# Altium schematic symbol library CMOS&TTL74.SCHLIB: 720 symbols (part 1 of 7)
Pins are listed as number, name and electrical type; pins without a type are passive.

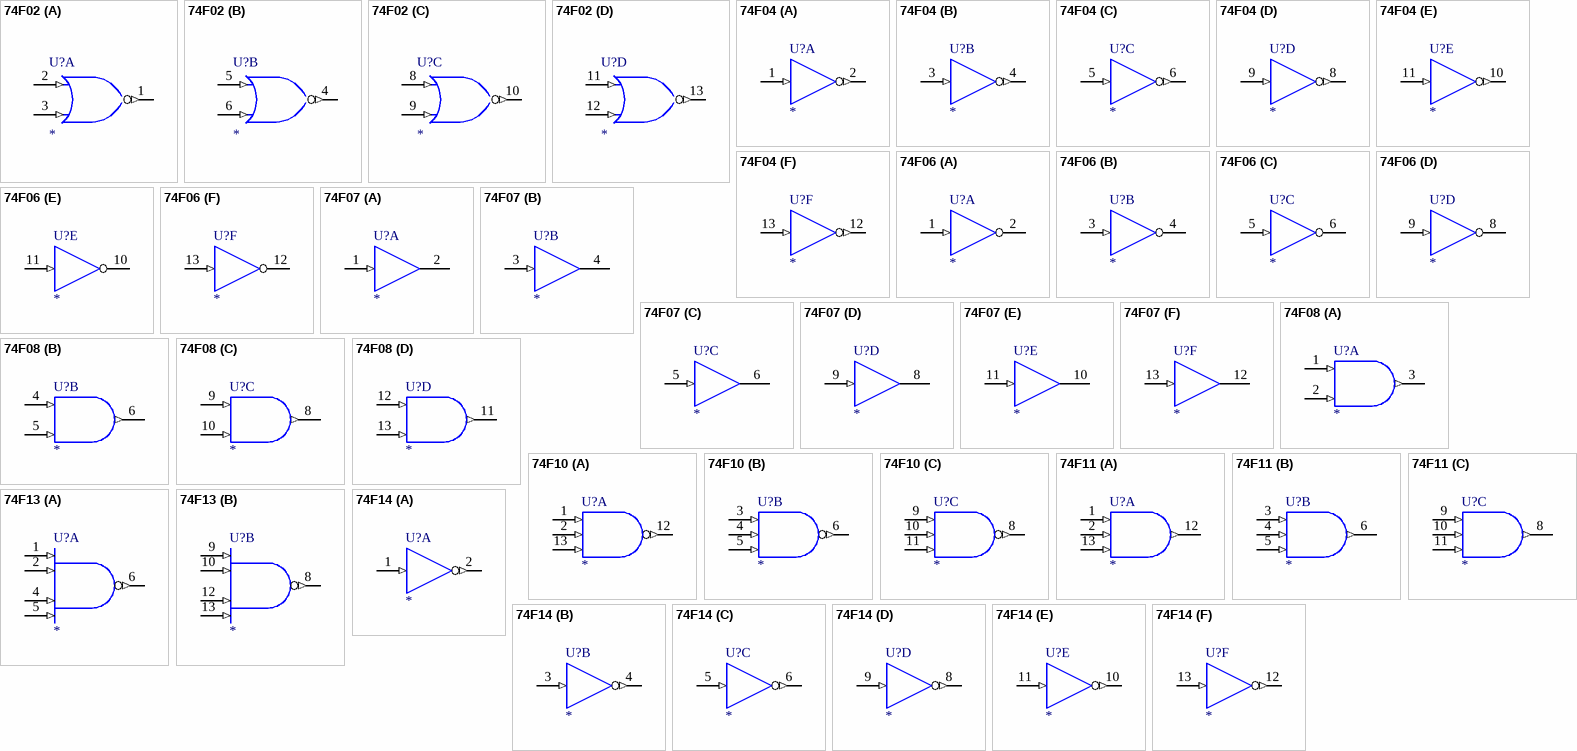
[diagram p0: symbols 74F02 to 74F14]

## 74F02
designator U?
Quad 2-Input NOR Gate
footprint DIP-14
simulation model 74F02 (SIMCODE)
part A pins: 1 Y (out), 2 A (in), 3 B (in), 7 GND (power) hidden to GND, 14 VCC (power) hidden to VCC
part B pins: 4 Y (out), 5 A (in), 6 B (in), 7 GND (power) hidden to GND, 14 VCC (power) hidden to VCC
part C pins: 7 GND (power) hidden to GND, 8 A (in), 9 B (in), 10 Y (out), 14 VCC (power) hidden to VCC
part D pins: 7 GND (power) hidden to GND, 11 A (in), 12 B (in), 13 Y (out), 14 VCC (power) hidden to VCC
1 alternate drawing of the same symbol

## 74F04
designator U?
Hex Inverter
footprint DIP-14
simulation model 74F04 (SIMCODE)
part A pins: 1 A (in), 2 Y (out), 7 GND (power) hidden to GND, 14 VCC (power) hidden to VCC
part B pins: 3 A (in), 4 Y (out), 7 GND (power) hidden to GND, 14 VCC (power) hidden to VCC
part C pins: 5 A (in), 6 Y (out), 7 GND (power) hidden to GND, 14 VCC (power) hidden to VCC
part D pins: 7 GND (power) hidden to GND, 8 Y (out), 9 A (in), 14 VCC (power) hidden to VCC
part E pins: 7 GND (power) hidden to GND, 10 Y (out), 11 A (in), 14 VCC (power) hidden to VCC
part F pins: 7 GND (power) hidden to GND, 12 Y (out), 13 A (in), 14 VCC (power) hidden to VCC
1 alternate drawing of the same symbol

## 74F06
designator U?
Hex Inverter with Open-Collector High-Voltage Output
footprint DIP-14
simulation model 74F06 (SIMCODE)
part A pins: 1 A (in), 2 Y (oc), 7 GND (power) hidden to GND, 14 VCC (power) hidden to VCC
part B pins: 3 A (in), 4 Y (oc), 7 GND (power) hidden to GND, 14 VCC (power) hidden to VCC
part C pins: 5 A (in), 6 Y (oc), 7 GND (power) hidden to GND, 14 VCC (power) hidden to VCC
part D pins: 7 GND (power) hidden to GND, 8 Y (oc), 9 A (in), 14 VCC (power) hidden to VCC
part E pins: 7 GND (power) hidden to GND, 10 Y (oc), 11 A (in), 14 VCC (power) hidden to VCC
part F pins: 7 GND (power) hidden to GND, 12 Y (oc), 13 A (in), 14 VCC (power) hidden to VCC
2 alternate drawings of the same symbol

## 74F07
designator U?
Hex Buffer/Driver with Open-Collector High-Voltage Output
footprint DIP-14
simulation model 74F07 (SIMCODE)
part A pins: 1 A (in), 2 Y (oc), 7 GND (power) hidden to GND, 14 VCC (power) hidden to VCC
part B pins: 3 A (in), 4 Y (oc), 7 GND (power) hidden to GND, 14 VCC (power) hidden to VCC
part C pins: 5 A (in), 6 Y (oc), 7 GND (power) hidden to GND, 14 VCC (power) hidden to VCC
part D pins: 7 GND (power) hidden to GND, 8 Y (oc), 9 A (in), 14 VCC (power) hidden to VCC
part E pins: 7 GND (power) hidden to GND, 10 Y (oc), 11 A (in), 14 VCC (power) hidden to VCC
part F pins: 7 GND (power) hidden to GND, 12 Y (oc), 13 A (in), 14 VCC (power) hidden to VCC
2 alternate drawings of the same symbol

## 74F08
designator U?
Quad 2-Input Positive-AND Gate
footprint DIP-14
simulation model 74F08 (SIMCODE)
part A pins: 1 A (in), 2 B (in), 3 Y (out), 7 GND (power) hidden to GND, 14 VCC (power) hidden to VCC
part B pins: 4 A (in), 5 B (in), 6 Y (out), 7 GND (power) hidden to GND, 14 VCC (power) hidden to VCC
part C pins: 7 GND (power) hidden to GND, 8 Y (out), 9 A (in), 10 B (in), 14 VCC (power) hidden to VCC
part D pins: 7 GND (power) hidden to GND, 11 Y (out), 12 A (in), 13 B (in), 14 VCC (power) hidden to VCC
1 alternate drawing of the same symbol

## 74F10
designator U?
Triple 3-Input Positive-NAND Gate
footprint DIP-14
simulation model 74F10 (SIMCODE)
part A pins: 1 A (in), 2 B (in), 7 GND (power) hidden to GND, 12 Y (out), 13 C (in), 14 VCC (power) hidden to VCC
part B pins: 3 A (in), 4 B (in), 5 C (in), 6 Y (out), 7 GND (power) hidden to GND, 14 VCC (power) hidden to VCC
part C pins: 7 GND (power) hidden to GND, 8 Y (out), 9 A (in), 10 B (in), 11 C (in), 14 VCC (power) hidden to VCC
1 alternate drawing of the same symbol

## 74F11
designator U?
Triple 3-Input Positive-AND Gate
footprint DIP-14
simulation model 74F11 (SIMCODE)
part A pins: 1 A (in), 2 B (in), 7 GND (power) hidden to GND, 12 Y (out), 13 C (in), 14 VCC (power) hidden to VCC
part B pins: 3 A (in), 4 B (in), 5 C (in), 6 Y (out), 7 GND (power) hidden to GND, 14 VCC (power) hidden to VCC
part C pins: 7 GND (power) hidden to GND, 8 Y (out), 9 A (in), 10 B (in), 11 C (in), 14 VCC (power) hidden to VCC
1 alternate drawing of the same symbol

## 74F13
designator U?
Dual 4-Input Positive-NAND Schmitt-Trigger
footprint DIP-14
simulation model 74F13 (SIMCODE)
part A pins: 1 A (in), 2 B (in), 4 C (in), 5 D (in), 6 Y (out), 7 GND (power) hidden to GND, 14 VCC (power) hidden to VCC
part B pins: 7 GND (power) hidden to GND, 8 Y (out), 9 A (in), 10 B (in), 12 C (in), 13 D (in), 14 VCC (power) hidden to VCC
1 alternate drawing of the same symbol

## 74F14
designator U?
Hex Schmitt-Trigger Inverter
footprint DIP-14
simulation model 74F14 (SIMCODE)
part A pins: 1 A (in), 2 Y (out), 7 GND (power) hidden to GND, 14 VCC (power) hidden to VCC
part B pins: 3 A (in), 4 Y (out), 7 GND (power) hidden to GND, 14 VCC (power) hidden to VCC
part C pins: 5 A (in), 6 Y (out), 7 GND (power) hidden to GND, 14 VCC (power) hidden to VCC
part D pins: 7 GND (power) hidden to GND, 8 Y (out), 9 A (in), 14 VCC (power) hidden to VCC
part E pins: 7 GND (power) hidden to GND, 10 Y (out), 11 A (in), 14 VCC (power) hidden to VCC
part F pins: 7 GND (power) hidden to GND, 12 Y (out), 13 A (in), 14 VCC (power) hidden to VCC
1 alternate drawing of the same symbol

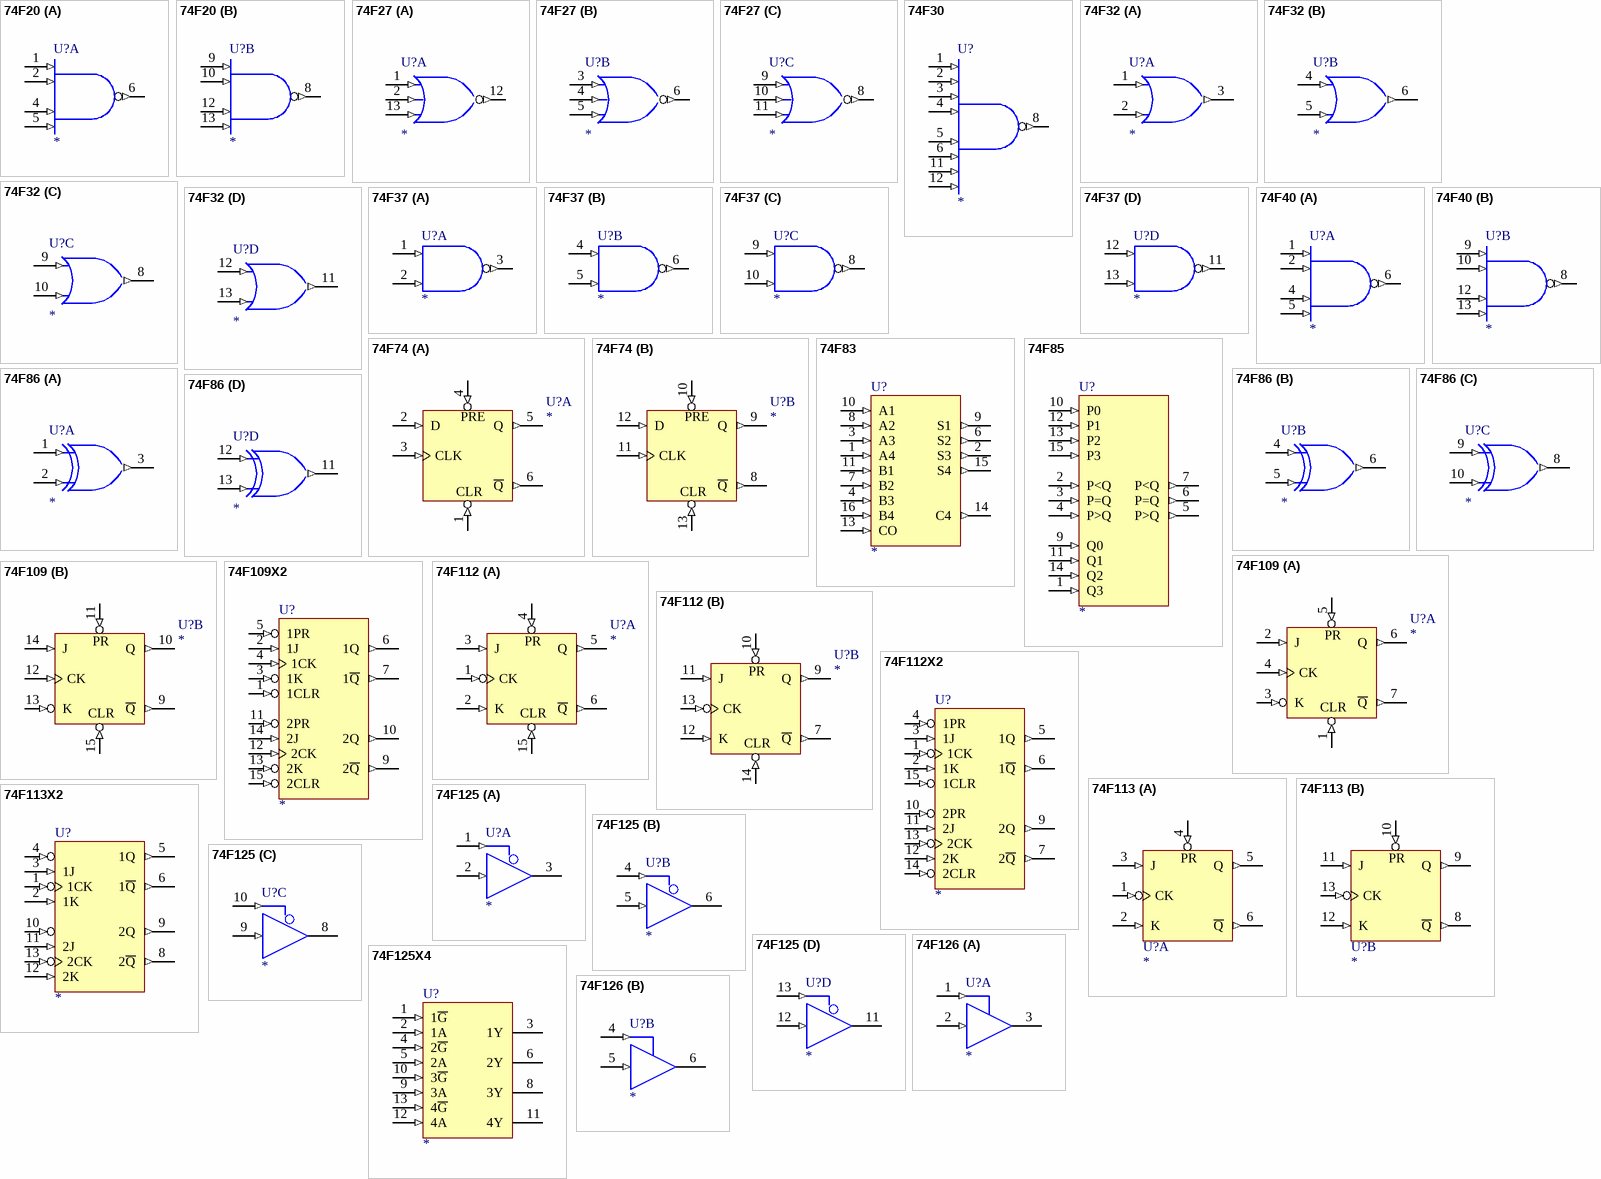
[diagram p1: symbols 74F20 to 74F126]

## 74F20
designator U?
Dual 4-Input Positive-NAND Gate
footprint DIP-14
simulation model 74F20 (SIMCODE)
part A pins: 1 A (in), 2 B (in), 4 C (in), 5 D (in), 6 Y (out), 7 GND (power) hidden to GND, 14 VCC (power) hidden to VCC
part B pins: 7 GND (power) hidden to GND, 8 Y (out), 9 A (in), 10 B (in), 12 C (in), 13 D (in), 14 VCC (power) hidden to VCC
2 alternate drawings of the same symbol

## 74F27
designator U?
Triple 3-Input Positive-NOR Gate
footprint DIP-14
simulation model 74F27 (SIMCODE)
part A pins: 1 A (in), 2 B (in), 7 GND (power) hidden to GND, 12 Y (out), 13 C (in), 14 VCC (power) hidden to VCC
part B pins: 3 A (in), 4 B (in), 5 C (in), 6 Y (out), 7 GND (power) hidden to GND, 14 VCC (power) hidden to VCC
part C pins: 7 GND (power) hidden to GND, 8 Y (out), 9 A (in), 10 B (in), 11 C (in), 14 VCC (power) hidden to VCC
1 alternate drawing of the same symbol

## 74F30
designator U?
8-Input Positive-NAND Gate
footprint DIP-14
simulation model 74F30 (SIMCODE)
pins: 1 A (in), 2 B (in), 3 C (in), 4 D (in), 5 E (in), 6 F (in), 7 GND (power) hidden to GND, 8 Y (out), 11 G (in), 12 H (in), 14 VCC (power) hidden to VCC
1 alternate drawing of the same symbol

## 74F32
designator U?
Quad 2-Input Positive-OR Gate
footprint DIP-14
simulation model 74F32 (SIMCODE)
part A pins: 1 A (in), 2 B (in), 3 Y (out), 7 GND (power) hidden to GND, 14 VCC (power) hidden to VCC
part B pins: 4 A (in), 5 B (in), 6 Y (out), 7 GND (power) hidden to GND, 14 VCC (power) hidden to VCC
part C pins: 7 GND (power) hidden to GND, 8 Y (out), 9 A (in), 10 B (in), 14 VCC (power) hidden to VCC
part D pins: 7 GND (power) hidden to GND, 11 Y (out), 12 A (in), 13 B (in), 14 VCC (power) hidden to VCC
1 alternate drawing of the same symbol

## 74F37
designator U?
Quad 2-Input Positive-NAND Buffer
footprint DIP-14
simulation model 74F37 (SIMCODE)
part A pins: 1 A (in), 2 B (in), 3 Y (out), 7 GND (power) hidden to GND, 14 VCC (power) hidden to VCC
part B pins: 4 A (in), 5 B (in), 6 Y (out), 7 GND (power) hidden to GND, 14 VCC (power) hidden to VCC
part C pins: 7 GND (power) hidden to GND, 8 Y (out), 9 A (in), 10 B (in), 14 VCC (power) hidden to VCC
part D pins: 7 GND (power) hidden to GND, 11 Y (out), 12 A (in), 13 B (in), 14 VCC (power) hidden to VCC
1 alternate drawing of the same symbol

## 74F40
designator U?
Dual 4-Input Positive-NAND Buffer
footprint DIP-14
simulation model 74F40 (SIMCODE)
part A pins: 1 A (in), 2 B (in), 4 C (in), 5 D (in), 6 Y (out), 7 GND (power) hidden to GND, 14 VCC (power) hidden to VCC
part B pins: 7 GND (power) hidden to GND, 8 Y (out), 9 A (in), 10 B (in), 12 C (in), 13 D (in), 14 VCC (power) hidden to VCC
2 alternate drawings of the same symbol

## 74F74
designator U?
Dual D-Type Positive-Edge-Triggered Flip-Flop with Clear and Preset
footprint DIP-14
simulation model 74F74 (SIMCODE)
part A pins: 1 ~{CLR} (in), 2 D (in), 3 CLK (in), 4 ~{PRE} (in), 5 Q (out), 6 ~{Q} (out), 7 GND (power) hidden to GND, 14 VCC (power) hidden to VCC
part B pins: 7 GND (power) hidden to GND, 8 ~{Q} (out), 9 Q (out), 10 ~{PRE} (in), 11 CLK (in), 12 D (in), 13 ~{CLR} (in), 14 VCC (power) hidden to VCC
1 alternate drawing of the same symbol

## 74F83
designator U?
4-Bit Binary Full Adder with Fast Carry
footprint DIP-16
simulation model 74F83 (SIMCODE)
pins: 1 A4 (in), 2 S3 (out), 3 A3 (in), 4 B3 (in), 5 VCC (power) hidden to VCC, 6 S2 (out), 7 B2 (in), 8 A2 (in), 9 S1 (out), 10 A1 (in), 11 B1 (in), 12 GND (power) hidden to GND, 13 CO (in), 14 C4 (out), 15 S4 (out), 16 B4 (in)
1 alternate drawing of the same symbol

## 74F85
designator U?
4-Bit Magnitude Comparator
footprint DIP-16
simulation model 74F85 (SIMCODE)
pins: 1 Q3 (in), 2 P<Q (in), 3 P=Q (in), 4 P>Q (in), 5 P>Q (out), 6 P=Q (out), 7 P<Q (out), 8 GND (power) hidden to GND, 9 Q0 (in), 10 P0 (in), 11 Q1 (in), 12 P1 (in), 13 P2 (in), 14 Q2 (in), 15 P3 (in), 16 VCC (power) hidden to VCC
1 alternate drawing of the same symbol

## 74F86
designator U?
Quad Exclusive-OR Gate
footprint DIP-14
simulation model 74F86 (SIMCODE)
part A pins: 1 A (in), 2 B (in), 3 Y (out), 7 GND (power) hidden to GND, 14 VCC (power) hidden to VCC
part B pins: 4 A (in), 5 B (in), 6 Y (out), 7 GND (power) hidden to GND, 14 VCC (power) hidden to VCC
part C pins: 7 GND (power) hidden to GND, 8 Y (out), 9 A (in), 10 B (in), 14 VCC (power) hidden to VCC
part D pins: 7 GND (power) hidden to GND, 11 Y (out), 12 A (in), 13 B (in), 14 VCC (power) hidden to VCC
1 alternate drawing of the same symbol

## 74F109
designator U?
Dual J-~K Positive-Edge-Triggered Flip Flop with Preset and Clear
footprint DIP-16
simulation model 74F109 (SIMCODE)
part A pins: 1 CLR (in), 2 J (in), 3 K (in), 4 CK (in), 5 PR (in), 6 Q (out), 7 ~{Q} (out), 8 GND (power) hidden to GND, 16 VCC (power) hidden to VCC
part B pins: 8 GND (power) hidden to GND, 9 ~{Q} (out), 10 Q (out), 11 PR (in), 12 CK (in), 13 K (in), 14 J (in), 15 CLR (in), 16 VCC (power) hidden to VCC
1 alternate drawing of the same symbol

## 74F109X2
designator U?
Dual J-~K Positive-Edge-Triggered Flip Flop with Preset and Clear
footprint DIP-16
simulation model 74F109X2 (SIMCODE)
pins: 1 1CLR (in), 2 1J (in), 3 1K (in), 4 1CK (in), 5 1PR (in), 6 1Q (out), 7 1~{Q} (out), 8 GND (power) hidden to GND, 9 2~{Q} (out), 10 2Q (out), 11 2PR (in), 12 2CK (in), 13 2K (in), 14 2J (in), 15 2CLR (in), 16 VCC (power) hidden to VCC
1 alternate drawing of the same symbol

## 74F112
designator U?
Dual J-K Negative-Edge-Triggered Flip-Flop with Clear and Preset
footprint DIP-16
simulation model 74F112 (SIMCODE)
part A pins: 1 CK (in), 2 K (in), 3 J (in), 4 PR (in), 5 Q (out), 6 ~{Q} (out), 8 GND (power) hidden to GND, 15 CLR (in), 16 VCC (power) hidden to VCC
part B pins: 7 ~{Q} (out), 8 GND (power) hidden to GND, 9 Q (out), 10 PR (in), 11 J (in), 12 K (in), 13 CK (in), 14 CLR (in), 16 VCC (power) hidden to VCC
1 alternate drawing of the same symbol

## 74F112X2
designator U?
Dual J-K Negative-Edge-Triggered Flip-Flop with Clear and Preset
footprint DIP-16
simulation model 74F112X2 (SIMCODE)
pins: 1 1CK (in), 2 1K (in), 3 1J (in), 4 1PR (in), 5 1Q (out), 6 1~{Q} (out), 7 2~{Q} (out), 8 GND (power) hidden to GND, 9 2Q (out), 10 2PR (in), 11 2J (in), 12 2K (in), 13 2CK (in), 14 2CLR (in), 15 1CLR (in), 16 VCC (power) hidden to VCC
1 alternate drawing of the same symbol

## 74F113
designator U?
Dual J-K Negative-Edge-Triggered Flip-Flop with Preset
footprint DIP-14
simulation model 74F113 (SIMCODE)
part A pins: 1 CK (in), 2 K (in), 3 J (in), 4 PR (in), 5 Q (out), 6 ~{Q} (out), 7 GND (power) hidden to GND, 14 VCC (power) hidden to VCC
part B pins: 7 GND (power) hidden to GND, 8 ~{Q} (out), 9 Q (out), 10 PR (in), 11 J (in), 12 K (in), 13 CK (in), 14 VCC (power) hidden to VCC
1 alternate drawing of the same symbol

## 74F113X2
designator U?
Dual J-K Negative-Edge-Triggered Flip-Flop with Preset
footprint DIP-14
simulation model 74F113X2 (SIMCODE)
pins: 1 1CK (in), 2 1K (in), 3 1J (in), 4 1PR (in), 5 1Q (out), 6 1~{Q} (out), 7 GND (power) hidden to GND, 8 2~{Q} (out), 9 2Q (out), 10 2PR (in), 11 2J (in), 12 2K (in), 13 2CK (in), 14 VCC (power) hidden to VCC
1 alternate drawing of the same symbol

## 74F125
designator U?
Quad Bus Buffer Gate with 3-State Output
footprint DIP-14
simulation model 74F125 (SIMCODE)
part A pins: 1 ~{G} (in), 2 A (in), 3 Y (hiz), 7 GND (power) hidden to GND, 14 VCC (power) hidden to VCC
part B pins: 4 ~{G} (in), 5 A (in), 6 Y (hiz), 7 GND (power) hidden to GND, 14 VCC (power) hidden to VCC
part C pins: 7 GND (power) hidden to GND, 8 Y (hiz), 9 A (in), 10 ~{G} (in), 14 VCC (power) hidden to VCC
part D pins: 7 GND (power) hidden to GND, 11 Y (hiz), 12 A (in), 13 ~{G} (in), 14 VCC (power) hidden to VCC
1 alternate drawing of the same symbol

## 74F125X4
designator U?
Quad Bus Buffer Gate with 3-State Output
footprint DIP-14
simulation model 74F125X4 (SIMCODE)
pins: 1 1~{G} (in), 2 1A (in), 3 1Y (hiz), 4 2~{G} (in), 5 2A (in), 6 2Y (hiz), 7 GND (power) hidden to GND, 8 3Y (hiz), 9 3A (in), 10 3~{G} (in), 11 4Y (hiz), 12 4A (in), 13 4~{G} (in), 14 VCC (power) hidden to VCC
1 alternate drawing of the same symbol

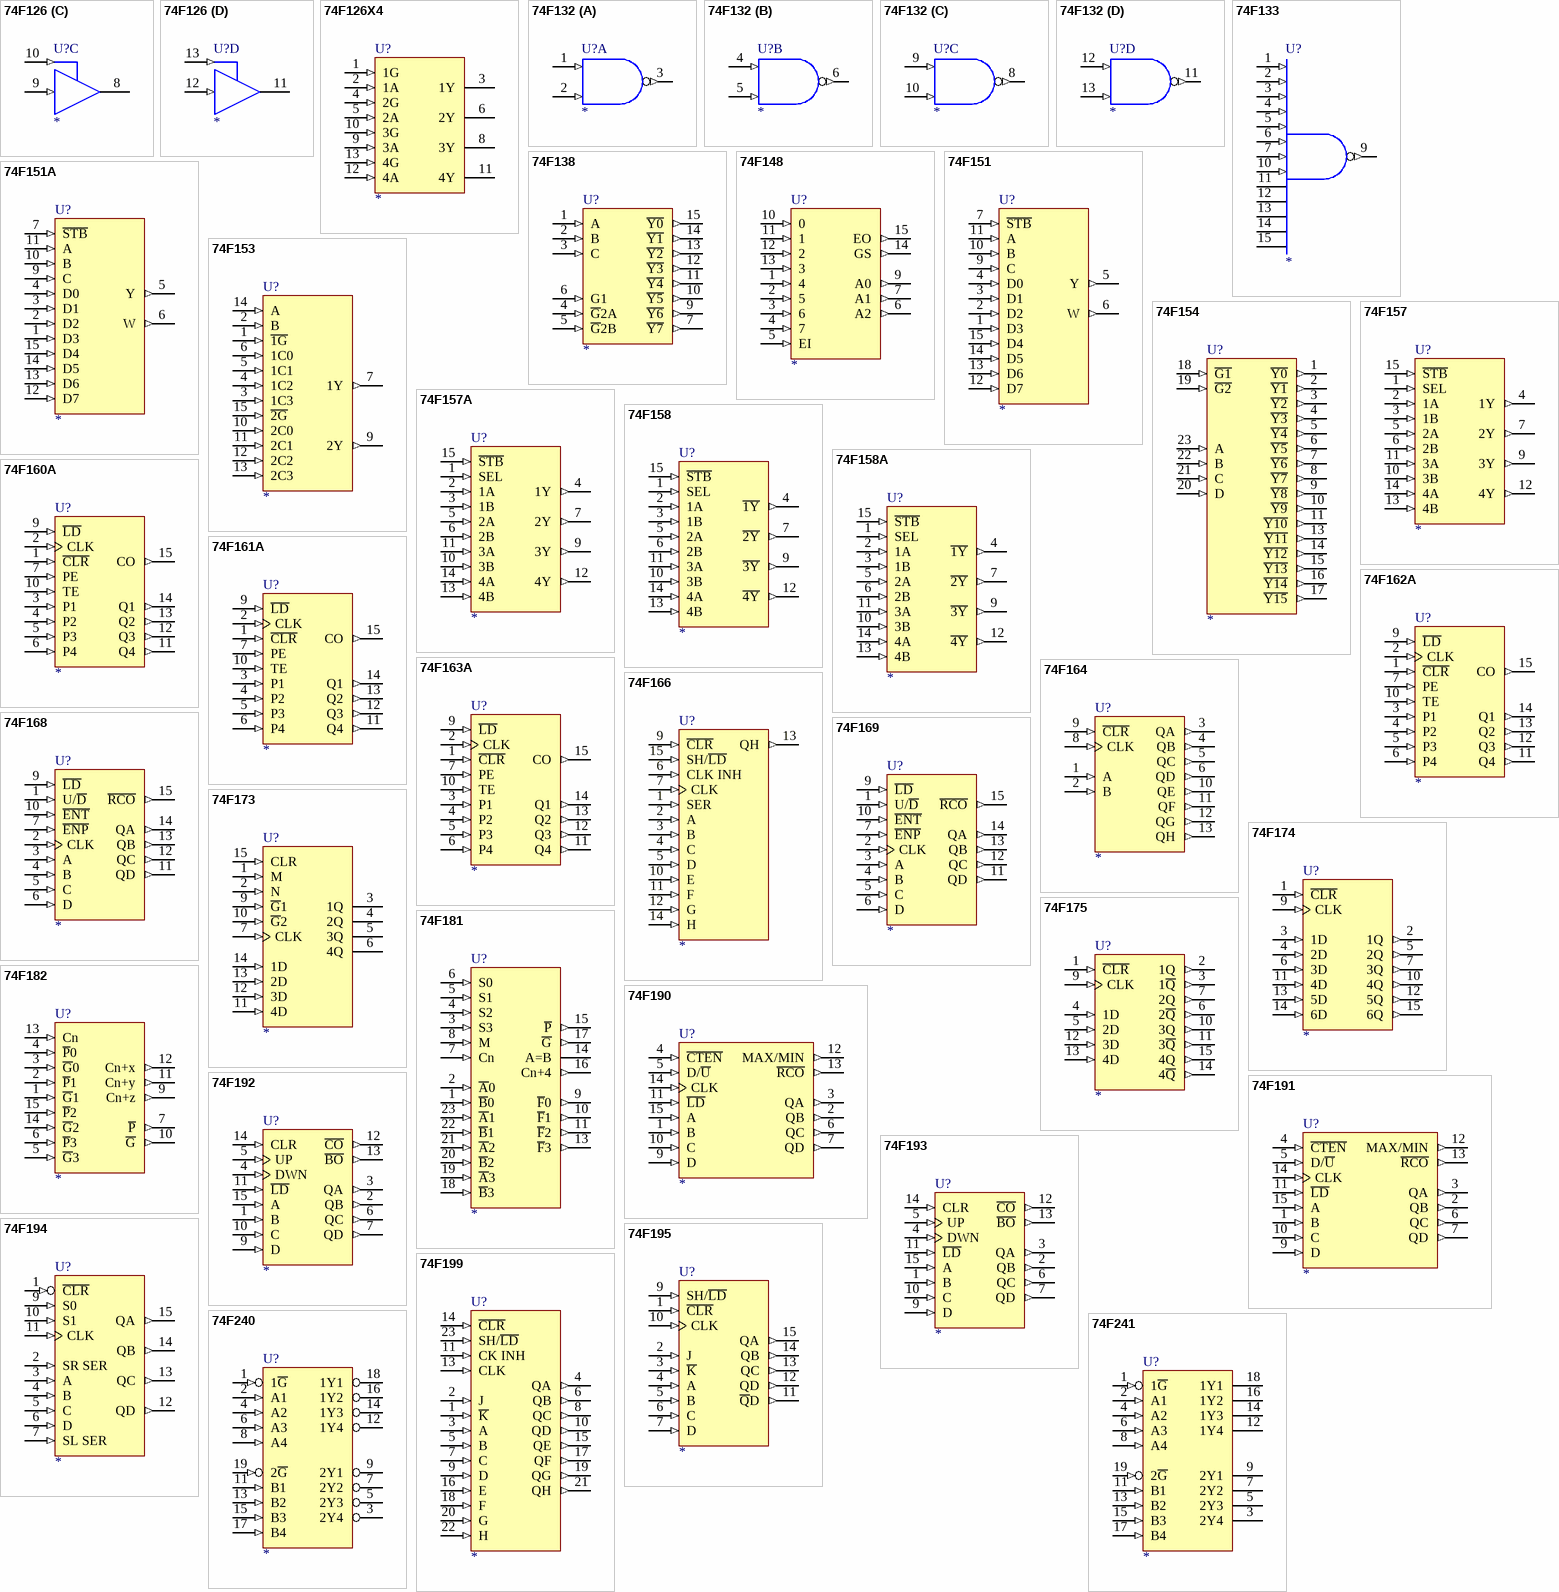
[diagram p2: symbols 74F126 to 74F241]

## 74F126
designator U?
Quad Bus Buffer Gate with 3-State Output
footprint DIP-14
simulation model 74F126 (SIMCODE)
part A pins: 1 G (in), 2 A (in), 3 Y (hiz), 7 GND (power) hidden to GND, 14 VCC (power) hidden to VCC
part B pins: 4 G (in), 5 A (in), 6 Y (hiz), 7 GND (power) hidden to GND, 14 VCC (power) hidden to VCC
part C pins: 7 GND (power) hidden to GND, 8 Y (hiz), 9 A (in), 10 G (in), 14 VCC (power) hidden to VCC
part D pins: 7 GND (power) hidden to GND, 11 Y (hiz), 12 A (in), 13 G (in), 14 VCC (power) hidden to VCC
1 alternate drawing of the same symbol

## 74F126X4
designator U?
Quad Bus Buffer Gate with 3-State Output
footprint DIP-14
simulation model 74F126X4 (SIMCODE)
pins: 1 1G (in), 2 1A (in), 3 1Y (hiz), 4 2G (in), 5 2A (in), 6 2Y (hiz), 7 GND (power) hidden to GND, 8 3Y (hiz), 9 3A (in), 10 3G (in), 11 4Y (hiz), 12 4A (in), 13 4G (in), 14 VCC (power) hidden to VCC
1 alternate drawing of the same symbol

## 74F132
designator U?
Quad Positive-NAND Gate with Schmitt-Trigger Input
footprint DIP-14
simulation model 74F132 (SIMCODE)
part A pins: 1 A (in), 2 B (in), 3 Y (out), 7 GND (power) hidden to GND, 14 VCC (power) hidden to VCC
part B pins: 4 A (in), 5 B (in), 6 Y (out), 7 GND (power) hidden to GND, 14 VCC (power) hidden to VCC
part C pins: 7 GND (power) hidden to GND, 8 Y (out), 9 A (in), 10 B (in), 14 VCC (power) hidden to VCC
part D pins: 7 GND (power) hidden to GND, 11 Y (out), 12 A (in), 13 B (in), 14 VCC (power) hidden to VCC
1 alternate drawing of the same symbol

## 74F133
designator U?
13-Input Positive-NAND Gate
footprint DIP-16
simulation model 74F133 (SIMCODE)
pins: 1 A (in), 2 B (in), 3 C (in), 4 D (in), 5 E (in), 6 F (in), 7 G (in), 8 GND (power) hidden to GND, 9 Y (out), 10 H (in), 11 I, 12 J, 13 K, 14 L, 15 M, 16 VCC (power) hidden to VCC
2 alternate drawings of the same symbol

## 74F138
designator U?
3-Line to 8-Line Decoder/Demultiplexer
footprint DIP-16
simulation model 74F138 (SIMCODE)
pins: 1 A (in), 2 B (in), 3 C (in), 4 ~{G}2A (in), 5 ~{G}2B (in), 6 G1 (in), 7 ~{Y7} (out), 8 GND (power) hidden to GND, 9 ~{Y6} (out), 10 ~{Y5} (out), 11 ~{Y4} (out), 12 ~{Y3} (out), 13 ~{Y2} (out), 14 ~{Y1} (out), 15 ~{Y0} (out), 16 VCC (power) hidden to VCC
1 alternate drawing of the same symbol

## 74F148
designator U?
8-Line to 3-Line Priority Encoder
footprint DIP-16
simulation model 74F148 (SIMCODE)
pins: 1 4 (in), 2 5 (in), 3 6 (in), 4 7 (in), 5 EI (in), 6 A2 (out), 7 A1 (out), 8 GND (power) hidden to GND, 9 A0 (out), 10 0 (in), 11 1 (in), 12 2 (in), 13 3 (in), 14 GS (out), 15 EO (out), 16 VCC (power) hidden to VCC
1 alternate drawing of the same symbol

## 74F151
designator U?
1 of 8 Data Selector/Multiplexer
footprint DIP-16
simulation model 74F151 (SIMCODE)
pins: 1 D3 (in), 2 D2 (in), 3 D1 (in), 4 D0 (in), 5 Y (out), 6 W (out), 7 ~{STB} (in), 8 GND (power) hidden to GND, 9 C (in), 10 B (in), 11 A (in), 12 D7 (in), 13 D6 (in), 14 D5 (in), 15 D4 (in), 16 VCC (power) hidden to VCC
1 alternate drawing of the same symbol

## 74F151A
designator U?
1 of 8 Data Selector/Multiplexer
footprint DIP-16
simulation model 74F151A (SIMCODE)
pins: 1 D3 (in), 2 D2 (in), 3 D1 (in), 4 D0 (in), 5 Y (out), 6 W (out), 7 ~{STB} (in), 8 GND (power) hidden to GND, 9 C (in), 10 B (in), 11 A (in), 12 D7 (in), 13 D6 (in), 14 D5 (in), 15 D4 (in), 16 VCC (power) hidden to VCC
1 alternate drawing of the same symbol

## 74F153
designator U?
Dual 4-Line to 1-Line Data Selector/Multiplexer
footprint DIP-16
simulation model 74F153 (SIMCODE)
pins: 1 ~{1G} (in), 2 B (in), 3 1C3 (in), 4 1C2 (in), 5 1C1 (in), 6 1C0 (in), 7 1Y (out), 8 GND (power) hidden to GND, 9 2Y (out), 10 2C0 (in), 11 2C1 (in), 12 2C2 (in), 13 2C3 (in), 14 A (in), 15 ~{2G} (in), 16 VCC (power) hidden to VCC
1 alternate drawing of the same symbol

## 74F154
designator U?
4-Line to 16-Line Decoder/Demultiplexer
footprint DIP-24
simulation model 74F154 (SIMCODE)
pins: 1 ~{Y0} (out), 2 ~{Y1} (out), 3 ~{Y2} (out), 4 ~{Y3} (out), 5 ~{Y4} (out), 6 ~{Y5} (out), 7 ~{Y6} (out), 8 ~{Y7} (out), 9 ~{Y8} (out), 10 ~{Y9} (out), 11 ~{Y10} (out), 12 GND (power) hidden to GND, 13 ~{Y11} (out), 14 ~{Y12} (out), 15 ~{Y13} (out), 16 ~{Y14} (out), 17 ~{Y15} (out), 18 ~{G1} (in), 19 ~{G2} (in), 20 D (in), 21 C (in), 22 B (in), 23 A (in), 24 VCC (power) hidden to VCC
1 alternate drawing of the same symbol

## 74F157
designator U?
Quad 2-Line to 1-Line Data Selector/Multiplexer
footprint DIP-16
simulation model 74F157 (SIMCODE)
pins: 1 SEL (in), 2 1A (in), 3 1B (in), 4 1Y (out), 5 2A (in), 6 2B (in), 7 2Y (out), 8 GND (power) hidden to GND, 9 3Y (out), 10 3B (in), 11 3A (in), 12 4Y (out), 13 4B (in), 14 4A (in), 15 ~{STB} (in), 16 VCC (power) hidden to VCC
1 alternate drawing of the same symbol

## 74F157A
designator U?
Quad 2-Line to 1-Line Data Selector/Multiplexer
footprint DIP-16
simulation model 74F157A (SIMCODE)
pins: 1 SEL (in), 2 1A (in), 3 1B (in), 4 1Y (out), 5 2A (in), 6 2B (in), 7 2Y (out), 8 GND (power) hidden to GND, 9 3Y (out), 10 3B (in), 11 3A (in), 12 4Y (out), 13 4B (in), 14 4A (in), 15 ~{STB} (in), 16 VCC (power) hidden to VCC
1 alternate drawing of the same symbol

## 74F158
designator U?
Quad 2-Line to 1-Line Data Selector/Multiplexer
footprint DIP-16
simulation model 74F158 (SIMCODE)
pins: 1 SEL (in), 2 1A (in), 3 1B (in), 4 ~{1Y} (out), 5 2A (in), 6 2B (in), 7 ~{2Y} (out), 8 GND (power) hidden to GND, 9 ~{3Y} (out), 10 3B (in), 11 3A (in), 12 ~{4Y} (out), 13 4B (in), 14 4A (in), 15 ~{STB} (in), 16 VCC (power) hidden to VCC
1 alternate drawing of the same symbol

## 74F158A
designator U?
Quad 2-Line to 1-Line Data Selector/Multiplexer
footprint DIP-16
simulation model 74F158A (SIMCODE)
pins: 1 SEL (in), 2 1A (in), 3 1B (in), 4 ~{1Y} (out), 5 2A (in), 6 2B (in), 7 ~{2Y} (out), 8 GND (power) hidden to GND, 9 ~{3Y} (out), 10 3B (in), 11 3A (in), 12 ~{4Y} (out), 13 4B (in), 14 4A (in), 15 ~{STB} (in), 16 VCC (power) hidden to VCC
1 alternate drawing of the same symbol

## 74F160A
designator U?
Synchronous 4-Bit Decade Counter with Direct Clear
footprint DIP-16
simulation model 74F160A (SIMCODE)
pins: 1 ~{CLR} (in), 2 CLK (in), 3 P1 (in), 4 P2 (in), 5 P3 (in), 6 P4 (in), 7 PE (in), 8 GND (power) hidden to GND, 9 ~{LD} (in), 10 TE (in), 11 Q4 (out), 12 Q3 (out), 13 Q2 (out), 14 Q1 (out), 15 CO (out), 16 VCC (power) hidden to VCC
1 alternate drawing of the same symbol

## 74F161A
designator U?
Synchronous 4-Bit Binary Counter with Direct Clear
footprint DIP-16
simulation model 74F161A (SIMCODE)
pins: 1 ~{CLR} (in), 2 CLK (in), 3 P1 (in), 4 P2 (in), 5 P3 (in), 6 P4 (in), 7 PE (in), 8 GND (power) hidden to GND, 9 ~{LD} (in), 10 TE (in), 11 Q4 (out), 12 Q3 (out), 13 Q2 (out), 14 Q1 (out), 15 CO (out), 16 VCC (power) hidden to VCC
1 alternate drawing of the same symbol

## 74F162A
designator U?
Fully Synchronous 4-Bit Decade Counter
footprint DIP-16
simulation model 74F162A (SIMCODE)
pins: 1 ~{CLR} (in), 2 CLK (in), 3 P1 (in), 4 P2 (in), 5 P3 (in), 6 P4 (in), 7 PE (in), 8 GND (power) hidden to GND, 9 ~{LD} (in), 10 TE (in), 11 Q4 (out), 12 Q3 (out), 13 Q2 (out), 14 Q1 (out), 15 CO (out), 16 VCC (power) hidden to VCC
1 alternate drawing of the same symbol

## 74F163A
designator U?
Fully Synchronous 4-Bit Binary Counter
footprint DIP-16
simulation model 74F163A (SIMCODE)
pins: 1 ~{CLR} (in), 2 CLK (in), 3 P1 (in), 4 P2 (in), 5 P3 (in), 6 P4 (in), 7 PE (in), 8 GND (power) hidden to GND, 9 ~{LD} (in), 10 TE (in), 11 Q4 (out), 12 Q3 (out), 13 Q2 (out), 14 Q1 (out), 15 CO (out), 16 VCC (power) hidden to VCC
1 alternate drawing of the same symbol

## 74F164
designator U?
8-Bit Parallel-Out Serial Shift Register
footprint DIP-14
simulation model 74F164 (SIMCODE)
pins: 1 A (in), 2 B (in), 3 QA (out), 4 QB (out), 5 QC (out), 6 QD (out), 7 GND (power) hidden to GND, 8 CLK (in), 9 ~{CLR} (in), 10 QE (out), 11 QF (out), 12 QG (out), 13 QH (out), 14 VCC (power) hidden to VCC
1 alternate drawing of the same symbol

## 74F166
designator U?
Parallel-Load 8-Bit Shift Register
footprint DIP-16
simulation model 74F166 (SIMCODE)
pins: 1 SER (in), 2 A (in), 3 B (in), 4 C (in), 5 D (in), 6 CLK INH (in), 7 CLK (in), 8 GND (power) hidden to GND, 9 ~{CLR} (in), 10 E (in), 11 F (in), 12 G (in), 13 QH (out), 14 H (in), 15 SH/~{LD} (in), 16 VCC (power) hidden to VCC
1 alternate drawing of the same symbol

## 74F168
designator U?
Synchronous 4-Bit Up/Down Decade Counter
footprint DIP-16
simulation model 74F168 (SIMCODE)
pins: 1 U/~{D} (in), 2 CLK (in), 3 A (in), 4 B (in), 5 C (in), 6 D (in), 7 ~{ENP} (in), 8 GND (power) hidden to GND, 9 ~{LD} (in), 10 ~{ENT} (in), 11 QD (out), 12 QC (out), 13 QB (out), 14 QA (out), 15 ~{RCO} (out), 16 VCC (power) hidden to VCC
1 alternate drawing of the same symbol

## 74F169
designator U?
Synchronous 4-Bit Up/Down Decade Counter
footprint DIP-16
simulation model 74F169 (SIMCODE)
pins: 1 U/~{D} (in), 2 CLK (in), 3 A (in), 4 B (in), 5 C (in), 6 D (in), 7 ~{ENP} (in), 8 GND (power) hidden to GND, 9 ~{LD} (in), 10 ~{ENT} (in), 11 QD (out), 12 QC (out), 13 QB (out), 14 QA (out), 15 ~{RCO} (out), 16 VCC (power) hidden to VCC
1 alternate drawing of the same symbol

## 74F173
designator U?
4-Bit D-Type Register with 3-State Outputs
footprint DIP-16
simulation model 74F173 (SIMCODE)
pins: 1 M (in), 2 N (in), 3 1Q (hiz), 4 2Q (hiz), 5 3Q (hiz), 6 4Q (hiz), 7 CLK (in), 8 GND (power) hidden to GND, 9 ~{G}1 (in), 10 ~{G}2 (in), 11 4D (in), 12 3D (in), 13 2D (in), 14 1D (in), 15 CLR (in), 16 VCC (power) hidden to VCC
1 alternate drawing of the same symbol

## 74F174
designator U?
Hex D-Type Flip-Flop with Clear
footprint DIP-16
simulation model 74F174 (SIMCODE)
pins: 1 ~{CLR} (in), 2 1Q (out), 3 1D (in), 4 2D (in), 5 2Q (out), 6 3D (in), 7 3Q (out), 8 GND (power) hidden to GND, 9 CLK (in), 10 4Q (out), 11 4D (in), 12 5Q (out), 13 5D (in), 14 6D (in), 15 6Q (out), 16 VCC (power) hidden to VCC
1 alternate drawing of the same symbol

## 74F175
designator U?
Quad D-Type Flip-Flop with Clear
footprint DIP-16
simulation model 74F175 (SIMCODE)
pins: 1 ~{CLR} (in), 2 1Q (out), 3 1~{Q} (out), 4 1D (in), 5 2D (in), 6 2~{Q} (out), 7 2Q (out), 8 GND (power) hidden to GND, 9 CLK (in), 10 3Q (out), 11 3~{Q} (out), 12 3D (in), 13 4D (in), 14 4~{Q} (out), 15 4Q (out), 16 VCC (power) hidden to VCC
1 alternate drawing of the same symbol

## 74F181
designator U?
Arithmetic Logic Unit/Function Generator
footprint DIP-24
simulation model 74F181 (SIMCODE)
pins: 1 ~{B}0 (in), 2 ~{A}0 (in), 3 S3 (in), 4 S2 (in), 5 S1 (in), 6 S0 (in), 7 Cn (in), 8 M (in), 9 ~{F}0 (out), 10 ~{F}1 (out), 11 ~{F}2 (out), 12 GND (power) hidden to GND, 13 ~{F}3 (out), 14 A=B (oc), 15 ~{P} (out), 16 Cn+4 (out), 17 ~{G} (out), 18 ~{B}3 (in), 19 ~{A}3 (in), 20 ~{B}2 (in), 21 ~{A}2 (in), 22 ~{B}1 (in), 23 ~{A}1 (in), 24 VCC (power) hidden to VCC
1 alternate drawing of the same symbol

## 74F182
designator U?
Look-Ahead Carry Generator
footprint DIP-16
simulation model 74F182 (SIMCODE)
pins: 1 ~{G}1 (in), 2 ~{P}1 (in), 3 ~{G}0 (in), 4 ~{P}0 (in), 5 ~{G}3 (in), 6 ~{P}3 (in), 7 ~{P} (out), 8 GND (power) hidden to GND, 9 Cn+z (out), 10 ~{G} (out), 11 Cn+y (out), 12 Cn+x (out), 13 Cn (in), 14 ~{G}2 (in), 15 ~{P}2 (in), 16 VCC (power) hidden to VCC
1 alternate drawing of the same symbol

## 74F190
designator U?
Synchronous 4-Bit Up/Down Decade Counter with Down/Up Mode Control
footprint DIP-16
simulation model 74F190 (SIMCODE)
pins: 1 B (in), 2 QB (out), 3 QA (out), 4 ~{CTEN} (in), 5 D/~{U} (in), 6 QC (out), 7 QD (out), 8 GND (power) hidden to GND, 9 D (in), 10 C (in), 11 ~{LD} (in), 12 MAX/MIN (out), 13 ~{RCO} (out), 14 CLK (in), 15 A (in), 16 VCC (power) hidden to VCC
1 alternate drawing of the same symbol

## 74F191
designator U?
Synchronous 4-Bit Up/Down Binary Counter with Down/Up Mode Control
footprint DIP-16
simulation model 74F191 (SIMCODE)
pins: 1 B (in), 2 QB (out), 3 QA (out), 4 ~{CTEN} (in), 5 D/~{U} (in), 6 QC (out), 7 QD (out), 8 GND (power) hidden to GND, 9 D (in), 10 C (in), 11 ~{LD} (in), 12 MAX/MIN (out), 13 ~{RCO} (out), 14 CLK (in), 15 A (in), 16 VCC (power) hidden to VCC
1 alternate drawing of the same symbol

## 74F192
designator U?
Synchronous 4-Bit Up/Down Decade Counter (Dual Clock with Clear)
footprint DIP-16
simulation model 74F192 (SIMCODE)
pins: 1 B (in), 2 QB (out), 3 QA (out), 4 DWN (in), 5 UP (in), 6 QC (out), 7 QD (out), 8 GND (power) hidden to GND, 9 D (in), 10 C (in), 11 ~{LD} (in), 12 ~{CO} (out), 13 ~{BO} (out), 14 CLR (in), 15 A (in), 16 VCC (power) hidden to VCC
1 alternate drawing of the same symbol

## 74F193
designator U?
Synchronous 4-Bit Up/Down Binary Counter (Dual Clock with Clear)
footprint DIP-16
simulation model 74F193 (SIMCODE)
pins: 1 B (in), 2 QB (out), 3 QA (out), 4 DWN (in), 5 UP (in), 6 QC (out), 7 QD (out), 8 GND (power) hidden to GND, 9 D (in), 10 C (in), 11 ~{LD} (in), 12 ~{CO} (out), 13 ~{BO} (out), 14 CLR (in), 15 A (in), 16 VCC (power) hidden to VCC
1 alternate drawing of the same symbol

## 74F194
designator U?
4-Bit Bidirectional Universal Shift Register
footprint DIP-16
simulation model 74F194 (SIMCODE)
pins: 1 ~{CLR} (in), 2 SR SER (in), 3 A (in), 4 B (in), 5 C (in), 6 D (in), 7 SL SER (in), 8 GND (power) hidden to GND, 9 S0 (in), 10 S1 (in), 11 CLK (in), 12 QD (out), 13 QC (out), 14 QB (out), 15 QA (out), 16 VCC (power) hidden to VCC
1 alternate drawing of the same symbol

## 74F195
designator U?
4-Bit Parallel-Access Shift Register
footprint DIP-16
simulation model 74F195 (SIMCODE)
pins: 1 ~{CLR} (in), 2 J (in), 3 ~{K} (in), 4 A (in), 5 B (in), 6 C (in), 7 D (in), 8 GND (power) hidden to GND, 9 SH/~{LD} (in), 10 CLK (in), 11 ~{Q}D (out), 12 QD (out), 13 QC (out), 14 QB (out), 15 QA (out), 16 VCC (power) hidden to VCC
1 alternate drawing of the same symbol

## 74F199
designator U?
8-Bit Shift Register
footprint DIP-24
simulation model 74F199 (SIMCODE)
pins: 1 ~{K} (in), 2 J (in), 3 A (in), 4 QA (out), 5 B (in), 6 QB (out), 7 C (in), 8 QC (out), 9 D (in), 10 QD (out), 11 CK INH (in), 12 GND (power) hidden to GND, 13 CLK (in), 14 ~{CLR} (in), 15 QE (out), 16 E (in), 17 QF (out), 18 F (in), 19 QG (out), 20 G (in), 21 QH (out), 22 H (in), 23 SH/~{LD} (in), 24 VCC (power) hidden to VCC
1 alternate drawing of the same symbol

## 74F240
designator U?
Octal Buffer and Line Driver with 3-State Output
footprint DIP-20
simulation model 74F240 (SIMCODE)
pins: 1 1~{G} (in), 2 A1 (in), 3 2Y4 (hiz), 4 A2 (in), 5 2Y3 (hiz), 6 A3 (in), 7 2Y2 (hiz), 8 A4 (in), 9 2Y1 (hiz), 10 GND (power) hidden to GND, 11 B1 (in), 12 1Y4 (hiz), 13 B2 (in), 14 1Y3 (hiz), 15 B3 (in), 16 1Y2 (hiz), 17 B4 (in), 18 1Y1 (hiz), 19 2~{G} (in), 20 VCC (power) hidden to VCC
1 alternate drawing of the same symbol

## 74F241
designator U?
Octal Buffer and Line Driver with 3-State Output
footprint DIP-20
simulation model 74F241 (SIMCODE)
pins: 1 1~{G} (in), 2 A1 (in), 3 2Y4 (hiz), 4 A2 (in), 5 2Y3 (hiz), 6 A3 (in), 7 2Y2 (hiz), 8 A4 (in), 9 2Y1 (hiz), 10 GND (power) hidden to GND, 11 B1 (in), 12 1Y4 (hiz), 13 B2 (in), 14 1Y3 (hiz), 15 B3 (in), 16 1Y2 (hiz), 17 B4 (in), 18 1Y1 (hiz), 19 2~{G} (in), 20 VCC (power) hidden to VCC
1 alternate drawing of the same symbol

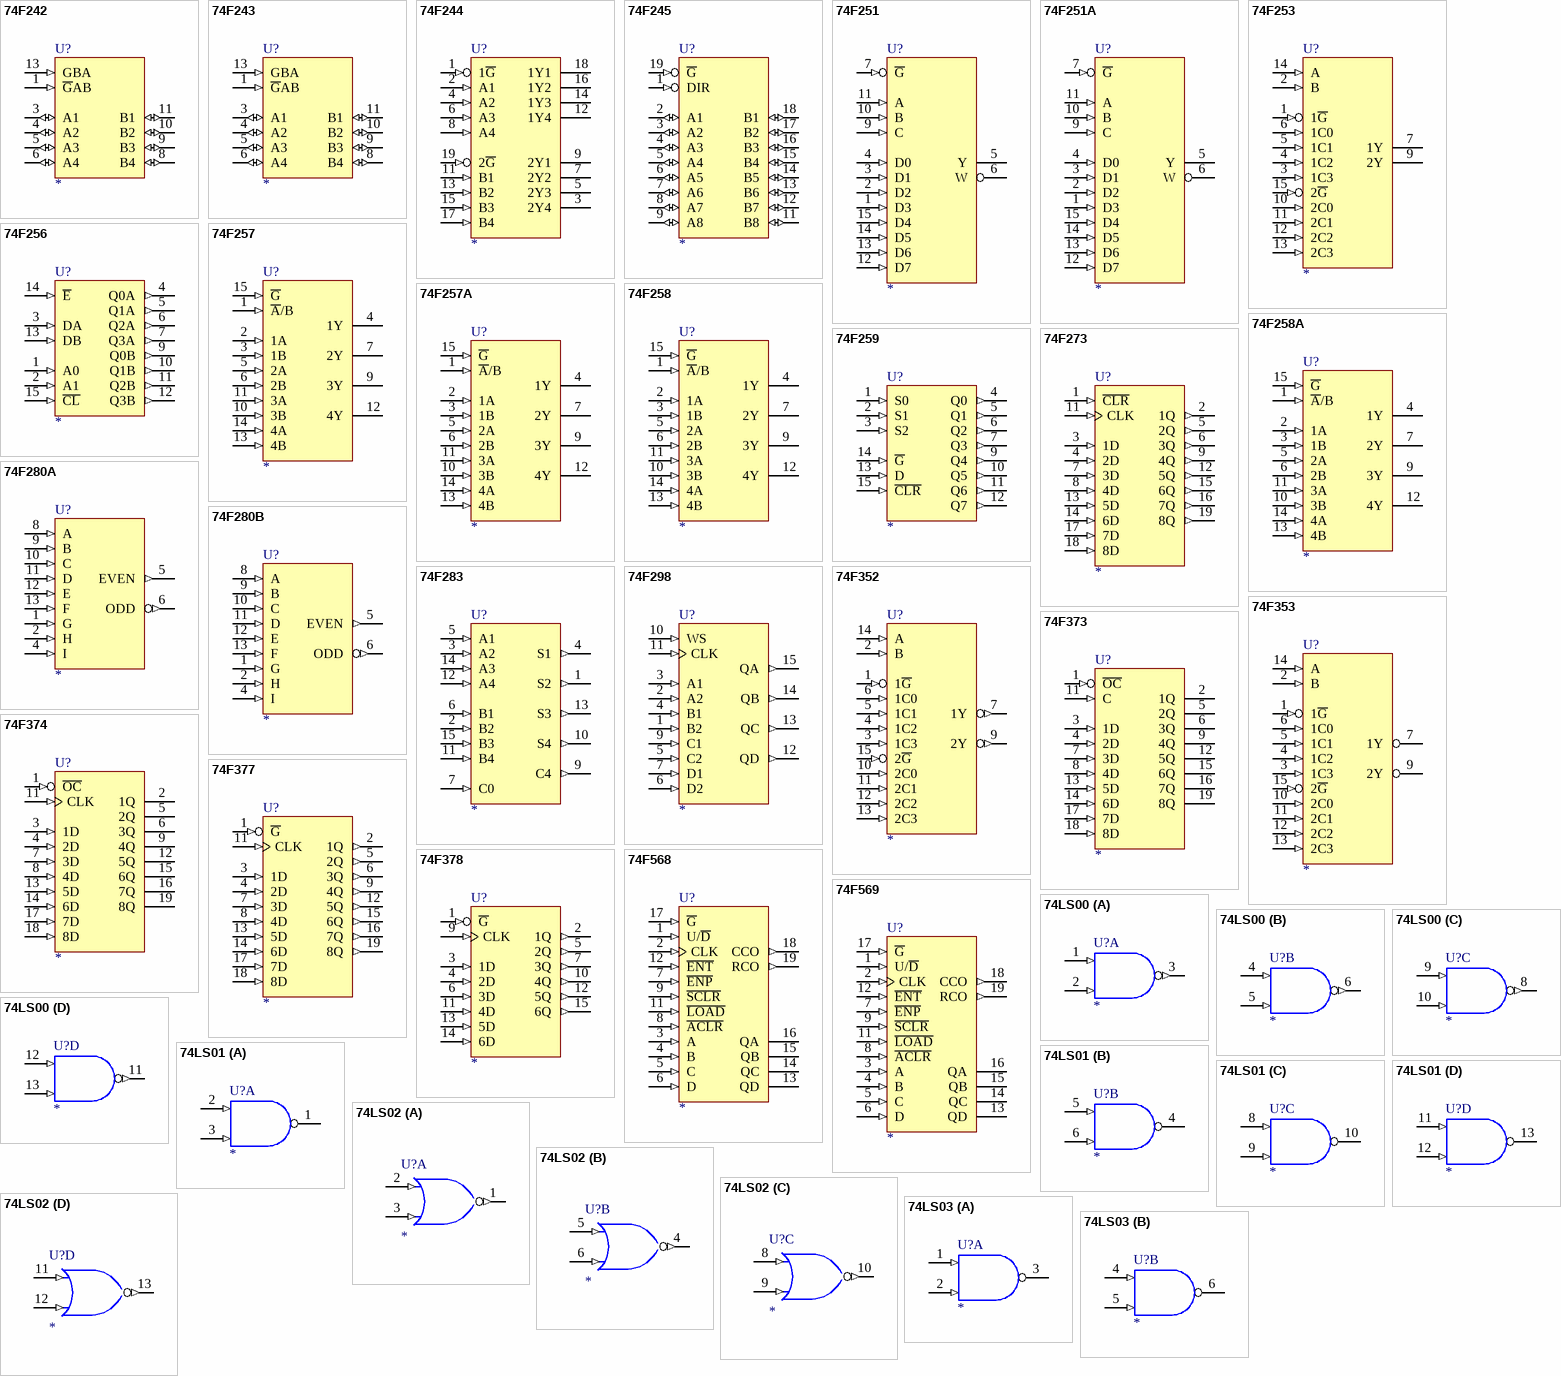
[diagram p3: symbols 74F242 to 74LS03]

## 74F242
designator U?
Quad Bus Transceiver
footprint DIP-14
simulation model 74F242 (SIMCODE)
pins: 1 ~{G}AB (in), 3 A1 (io), 4 A2 (io), 5 A3 (io), 6 A4 (io), 7 GND (power) hidden to GND, 8 B4 (io), 9 B3 (io), 10 B2 (io), 11 B1 (io), 13 GBA (in), 14 VCC (power) hidden to VCC
1 alternate drawing of the same symbol

## 74F243
designator U?
Quad Bus Transceiver
footprint DIP-14
simulation model 74F243 (SIMCODE)
pins: 1 ~{G}AB (in), 3 A1 (io), 4 A2 (io), 5 A3 (io), 6 A4 (io), 7 GND (power) hidden to GND, 8 B4 (io), 9 B3 (io), 10 B2 (io), 11 B1 (io), 13 GBA (in), 14 VCC (power) hidden to VCC
1 alternate drawing of the same symbol

## 74F244
designator U?
Octal Buffer and Line Driver with 3-State Output
footprint DIP-20
simulation model 74F244 (SIMCODE)
pins: 1 1~{G} (in), 2 A1 (in), 3 2Y4 (hiz), 4 A2 (in), 5 2Y3 (hiz), 6 A3 (in), 7 2Y2 (hiz), 8 A4 (in), 9 2Y1 (hiz), 10 GND (power) hidden to GND, 11 B1 (in), 12 1Y4 (hiz), 13 B2 (in), 14 1Y3 (hiz), 15 B3 (in), 16 1Y2 (hiz), 17 B4 (in), 18 1Y1 (hiz), 19 2~{G} (in), 20 VCC (power) hidden to VCC
1 alternate drawing of the same symbol

## 74F245
designator U?
Octal Bus Transceiver with 3-State Output
footprint DIP-20
simulation model 74F245 (SIMCODE)
pins: 1 DIR (in), 2 A1 (io), 3 A2 (io), 4 A3 (io), 5 A4 (io), 6 A5 (io), 7 A6 (io), 8 A7 (io), 9 A8 (io), 10 GND (power) hidden to GND, 11 B8 (io), 12 B7 (io), 13 B6 (io), 14 B5 (io), 15 B4 (io), 16 B3 (io), 17 B2 (io), 18 B1 (io), 19 ~{G} (in), 20 VCC (power) hidden to VCC
1 alternate drawing of the same symbol

## 74F251
designator U?
1-of-8 Data Selectors/Multiplexers with 3-State Output
footprint DIP-16
simulation model 74F251 (SIMCODE)
pins: 1 D3 (in), 2 D2 (in), 3 D1 (in), 4 D0 (in), 5 Y (hiz), 6 W (hiz), 7 ~{G} (in), 8 GND (power) hidden to GND, 9 C (in), 10 B (in), 11 A (in), 12 D7 (in), 13 D6 (in), 14 D5 (in), 15 D4 (in), 16 VCC (power) hidden to VCC
1 alternate drawing of the same symbol

## 74F251A
designator U?
1-of-8 Data Selectors/Multiplexers with 3-State Output
footprint DIP-16
simulation model 74F251A (SIMCODE)
pins: 1 D3 (in), 2 D2 (in), 3 D1 (in), 4 D0 (in), 5 Y (hiz), 6 W (hiz), 7 ~{G} (in), 8 GND (power) hidden to GND, 9 C (in), 10 B (in), 11 A (in), 12 D7 (in), 13 D6 (in), 14 D5 (in), 15 D4 (in), 16 VCC (power) hidden to VCC
1 alternate drawing of the same symbol

## 74F253
designator U?
Dual 4-Line to 1-Line Data Selector/Multiplexer with 3-State Output
footprint DIP-16
simulation model 74F253 (SIMCODE)
pins: 1 1~{G} (in), 2 B (in), 3 1C3 (in), 4 1C2 (in), 5 1C1 (in), 6 1C0 (in), 7 1Y (hiz), 8 GND (power) hidden to GND, 9 2Y (hiz), 10 2C0 (in), 11 2C1 (in), 12 2C2 (in), 13 2C3 (in), 14 A (in), 15 2~{G} (in), 16 VCC (power) hidden to VCC
1 alternate drawing of the same symbol

## 74F256
designator U?
Dual 4-Bit Addressable Latch
footprint DIP-16
simulation model 74F256 (SIMCODE)
pins: 1 A0 (in), 2 A1 (in), 3 DA (in), 4 Q0A (out), 5 Q1A (out), 6 Q2A (out), 7 Q3A (out), 8 GND (power) hidden to GND, 9 Q0B (out), 10 Q1B (out), 11 Q2B (out), 12 Q3B (out), 13 DB (in), 14 ~{E} (in), 15 ~{CL} (in), 16 VCC (power) hidden to VCC

## 74F257
designator U?
Quad 2-Line to 1-Line Data/Selector/Multiplexer with 3-State Output
footprint DIP-16
simulation model 74F257 (SIMCODE)
pins: 1 ~{A}/B (in), 2 1A (in), 3 1B (in), 4 1Y (hiz), 5 2A (in), 6 2B (in), 7 2Y (hiz), 8 GND (power) hidden to GND, 9 3Y (hiz), 10 3B (in), 11 3A (in), 12 4Y (hiz), 13 4B (in), 14 4A (in), 15 ~{G} (in), 16 VCC (power) hidden to VCC
1 alternate drawing of the same symbol

## 74F257A
designator U?
Quad 2-Line to 1-Line Data/Selector/Multiplexer with 3-State Output
footprint DIP-16
simulation model 74F257A (SIMCODE)
pins: 1 ~{A}/B (in), 2 1A (in), 3 1B (in), 4 1Y (hiz), 5 2A (in), 6 2B (in), 7 2Y (hiz), 8 GND (power) hidden to GND, 9 3Y (hiz), 10 3B (in), 11 3A (in), 12 4Y (hiz), 13 4B (in), 14 4A (in), 15 ~{G} (in), 16 VCC (power) hidden to VCC
1 alternate drawing of the same symbol

## 74F258
designator U?
Quad 2-Line to 1-Line Data/Selector/Multiplexer with 3-State Output
footprint DIP-16
simulation model 74F258 (SIMCODE)
pins: 1 ~{A}/B (in), 2 1A (in), 3 1B (in), 4 1Y (hiz), 5 2A (in), 6 2B (in), 7 2Y (hiz), 8 GND (power) hidden to GND, 9 3Y (hiz), 10 3B (in), 11 3A (in), 12 4Y (hiz), 13 4B (in), 14 4A (in), 15 ~{G} (in), 16 VCC (power) hidden to VCC
1 alternate drawing of the same symbol

## 74F258A
designator U?
Quad 2-Line to 1-Line Data/Selector/Multiplexer with 3-State Output
footprint DIP-16
simulation model 74F258A (SIMCODE)
pins: 1 ~{A}/B (in), 2 1A (in), 3 1B (in), 4 1Y (hiz), 5 2A (in), 6 2B (in), 7 2Y (hiz), 8 GND (power) hidden to GND, 9 3Y (hiz), 10 3B (in), 11 3A (in), 12 4Y (hiz), 13 4B (in), 14 4A (in), 15 ~{G} (in), 16 VCC (power) hidden to VCC
1 alternate drawing of the same symbol

## 74F259
designator U?
8-Bit Addressable Latch
footprint DIP-16
simulation model 74F259 (SIMCODE)
pins: 1 S0 (in), 2 S1 (in), 3 S2 (in), 4 Q0 (out), 5 Q1 (out), 6 Q2 (out), 7 Q3 (out), 8 GND (power) hidden to GND, 9 Q4 (out), 10 Q5 (out), 11 Q6 (out), 12 Q7 (out), 13 D (in), 14 ~{G} (in), 15 ~{CLR} (in), 16 VCC (power) hidden to VCC
1 alternate drawing of the same symbol

## 74F273
designator U?
Octal D-Type Flip-Flop with Clear
footprint DIP-20
simulation model 74F273 (SIMCODE)
pins: 1 ~{CLR} (in), 2 1Q (out), 3 1D (in), 4 2D (in), 5 2Q (out), 6 3Q (out), 7 3D (in), 8 4D (in), 9 4Q (out), 10 GND (power) hidden to GND, 11 CLK (in), 12 5Q (out), 13 5D (in), 14 6D (in), 15 6Q (out), 16 7Q (out), 17 7D (in), 18 8D (in), 19 8Q (out), 20 VCC (power) hidden to VCC
1 alternate drawing of the same symbol

## 74F280A
designator U?
9-Bit Odd/Even Parity Generator/Checker
footprint DIP-14
simulation model 74F280A (SIMCODE)
pins: 1 G (in), 2 H (in), 4 I (in), 5 EVEN (out), 6 ODD (out), 7 GND (power) hidden to GND, 8 A (in), 9 B (in), 10 C (in), 11 D (in), 12 E (in), 13 F (in), 14 VCC (power) hidden to VCC
1 alternate drawing of the same symbol

## 74F280B
designator U?
9-Bit Odd/Even Parity Generator/Checker
footprint DIP-14
simulation model 74F280B (SIMCODE)
pins: 1 G (in), 2 H (in), 4 I (in), 5 EVEN (out), 6 ODD (out), 7 GND (power) hidden to GND, 8 A (in), 9 B (in), 10 C (in), 11 D (in), 12 E (in), 13 F (in), 14 VCC (power) hidden to VCC
1 alternate drawing of the same symbol

## 74F283
designator U?
4-Bit Binary Full Adder with Fast Carry
footprint DIP-16
simulation model 74F283 (SIMCODE)
pins: 1 S2 (out), 2 B2 (in), 3 A2 (in), 4 S1 (out), 5 A1 (in), 6 B1 (in), 7 C0 (in), 8 GND (power) hidden to GND, 9 C4 (out), 10 S4 (out), 11 B4 (in), 12 A4 (in), 13 S3 (out), 14 A3 (in), 15 B3 (in), 16 VCC (power) hidden to VCC
1 alternate drawing of the same symbol

## 74F298
designator U?
Quad 2-Input Multiplexer with Storage
footprint DIP-16
simulation model 74F298 (SIMCODE)
pins: 1 B2 (in), 2 A2 (in), 3 A1 (in), 4 B1 (in), 5 C2 (in), 6 D2 (in), 7 D1 (in), 8 GND (power) hidden to GND, 9 C1 (in), 10 WS (in), 11 CLK (in), 12 QD (out), 13 QC (out), 14 QB (out), 15 QA (out), 16 VCC (power) hidden to VCC
1 alternate drawing of the same symbol

## 74F352
designator U?
Dual 4-Line to 1-Line Data Selector/Multiplexer
footprint DIP-16
simulation model 74F352 (SIMCODE)
pins: 1 1~{G} (in), 2 B (in), 3 1C3 (in), 4 1C2 (in), 5 1C1 (in), 6 1C0 (in), 7 1Y (out), 8 GND (power) hidden to GND, 9 2Y (out), 10 2C0 (in), 11 2C1 (in), 12 2C2 (in), 13 2C3 (in), 14 A (in), 15 2~{G} (in), 16 VCC (power) hidden to VCC
1 alternate drawing of the same symbol

## 74F353
designator U?
Dual 4-Line to 1-Line Data Selector/Multiplexer with 3-State Output
footprint DIP-16
simulation model 74F353 (SIMCODE)
pins: 1 1~{G} (in), 2 B (in), 3 1C3 (in), 4 1C2 (in), 5 1C1 (in), 6 1C0 (in), 7 1Y (hiz), 8 GND (power) hidden to GND, 9 2Y (hiz), 10 2C0 (in), 11 2C1 (in), 12 2C2 (in), 13 2C3 (in), 14 A (in), 15 2~{G} (in), 16 VCC (power) hidden to VCC
1 alternate drawing of the same symbol

## 74F373
designator U?
Octal D-Type Transparent Latch with 3-State Output
footprint DIP-20
simulation model 74F373 (SIMCODE)
pins: 1 ~{OC} (in), 2 1Q (hiz), 3 1D (in), 4 2D (in), 5 2Q (hiz), 6 3Q (hiz), 7 3D (in), 8 4D (in), 9 4Q (hiz), 10 GND (power) hidden to GND, 11 C (in), 12 5Q (hiz), 13 5D (in), 14 6D (in), 15 6Q (hiz), 16 7Q (hiz), 17 7D (in), 18 8D (in), 19 8Q (hiz), 20 VCC (power) hidden to VCC
1 alternate drawing of the same symbol

## 74F374
designator U?
Octal D-Type Edge-Triggered Flip-Flop with 3-State Output
footprint DIP-20
simulation model 74F374 (SIMCODE)
pins: 1 ~{OC} (in), 2 1Q (hiz), 3 1D (in), 4 2D (in), 5 2Q (hiz), 6 3Q (hiz), 7 3D (in), 8 4D (in), 9 4Q (hiz), 10 GND (power) hidden to GND, 11 CLK (in), 12 5Q (hiz), 13 5D (in), 14 6D (in), 15 6Q (hiz), 16 7Q (hiz), 17 7D (in), 18 8D (in), 19 8Q (hiz), 20 VCC (power) hidden to VCC
1 alternate drawing of the same symbol

## 74F377
designator U?
Octal D-Type Flip-Flop with Enable
footprint DIP-20
simulation model 74F377 (SIMCODE)
pins: 1 ~{G} (in), 2 1Q (out), 3 1D (in), 4 2D (in), 5 2Q (out), 6 3Q (out), 7 3D (in), 8 4D (in), 9 4Q (out), 10 GND (power) hidden to GND, 11 CLK (in), 12 5Q (out), 13 5D (in), 14 6D (in), 15 6Q (out), 16 7Q (out), 17 7D (in), 18 8D (in), 19 8Q (out), 20 VCC (power) hidden to VCC
1 alternate drawing of the same symbol

## 74F378
designator U?
Hex D-Type Flip Flop with Enable
footprint DIP-16
simulation model 74F378 (SIMCODE)
pins: 1 ~{G} (in), 2 1Q (out), 3 1D (in), 4 2D (in), 5 2Q (out), 6 3D (in), 7 3Q (out), 8 GND (power) hidden to GND, 9 CLK (in), 10 4Q (out), 11 4D (in), 12 5Q (out), 13 5D (in), 14 6D (in), 15 6Q (out), 16 VCC (power) hidden to VCC
1 alternate drawing of the same symbol

## 74F568
designator U?
Synchronous 4-Bit Up/Down Decade Counter with 3-State Outputs
footprint DIP-20
simulation model 74F568 (SIMCODE)
pins: 1 U/~{D} (in), 2 CLK (in), 3 A (in), 4 B (in), 5 C (in), 6 D (in), 7 ~{ENP} (in), 8 ~{ACLR} (in), 9 ~{SCLR} (in), 10 GND (power) hidden to GND, 11 ~{LOAD} (in), 12 ~{ENT} (in), 13 QD (hiz), 14 QC (hiz), 15 QB (hiz), 16 QA (hiz), 17 ~{G} (in), 18 CCO (out), 19 RCO (out), 20 VCC (power) hidden to VCC
1 alternate drawing of the same symbol

## 74F569
designator U?
Synchronous 4-Bit Up/Down Binary Counter with 3-State Outputs
footprint DIP-20
simulation model 74F569 (SIMCODE)
pins: 1 U/~{D} (in), 2 CLK (in), 3 A (in), 4 B (in), 5 C (in), 6 D (in), 7 ~{ENP} (in), 8 ~{ACLR} (in), 9 ~{SCLR} (in), 10 GND (power) hidden to GND, 11 ~{LOAD} (in), 12 ~{ENT} (in), 13 QD (hiz), 14 QC (hiz), 15 QB (hiz), 16 QA (hiz), 17 ~{G} (in), 18 CCO (out), 19 RCO (out), 20 VCC (power) hidden to VCC
1 alternate drawing of the same symbol

## 74LS00
designator U?
Quad 2-Input Positive-NAND Gate
footprint DIP-14
simulation model 74LS00 (SIMCODE)
part A pins: 1 A (in), 2 B (in), 3 Y (out), 7 GND (power) hidden to GND, 14 VCC (power) hidden to VCC
part B pins: 4 A (in), 5 B (in), 6 Y (out), 7 GND (power) hidden to GND, 14 VCC (power) hidden to VCC
part C pins: 7 GND (power) hidden to GND, 8 Y (out), 9 A (in), 10 B (in), 14 VCC (power) hidden to VCC
part D pins: 7 GND (power) hidden to GND, 11 Y (out), 12 A (in), 13 B (in), 14 VCC (power) hidden to VCC
1 alternate drawing of the same symbol

## 74LS01
designator U?
Quad 2-Input Positive-NAND Gate with Open-Collector Output
footprint DIP-14
simulation model 74LS01 (SIMCODE)
part A pins: 1 Y (oc), 2 A (in), 3 B (in), 7 GND (power) hidden to GND, 14 VCC (power) hidden to VCC
part B pins: 4 Y (oc), 5 A (in), 6 B (in), 7 GND (power) hidden to GND, 14 VCC (power) hidden to VCC
part C pins: 7 GND (power) hidden to GND, 8 A (in), 9 B (in), 10 Y (oc), 14 VCC (power) hidden to VCC
part D pins: 7 GND (power) hidden to GND, 11 A (in), 12 B (in), 13 Y (oc), 14 VCC (power) hidden to VCC
1 alternate drawing of the same symbol

## 74LS02
designator U?
Quad 2-Input NOR Gate
footprint DIP-14
simulation model 74LS02 (SIMCODE)
part A pins: 1 Y (out), 2 A (in), 3 B (in), 7 GND (power) hidden to GND, 14 VCC (power) hidden to VCC
part B pins: 4 Y (out), 5 A (in), 6 B (in), 7 GND (power) hidden to GND, 14 VCC (power) hidden to VCC
part C pins: 7 GND (power) hidden to GND, 8 A (in), 9 B (in), 10 Y (out), 14 VCC (power) hidden to VCC
part D pins: 7 GND (power) hidden to GND, 11 A (in), 12 B (in), 13 Y (out), 14 VCC (power) hidden to VCC
1 alternate drawing of the same symbol

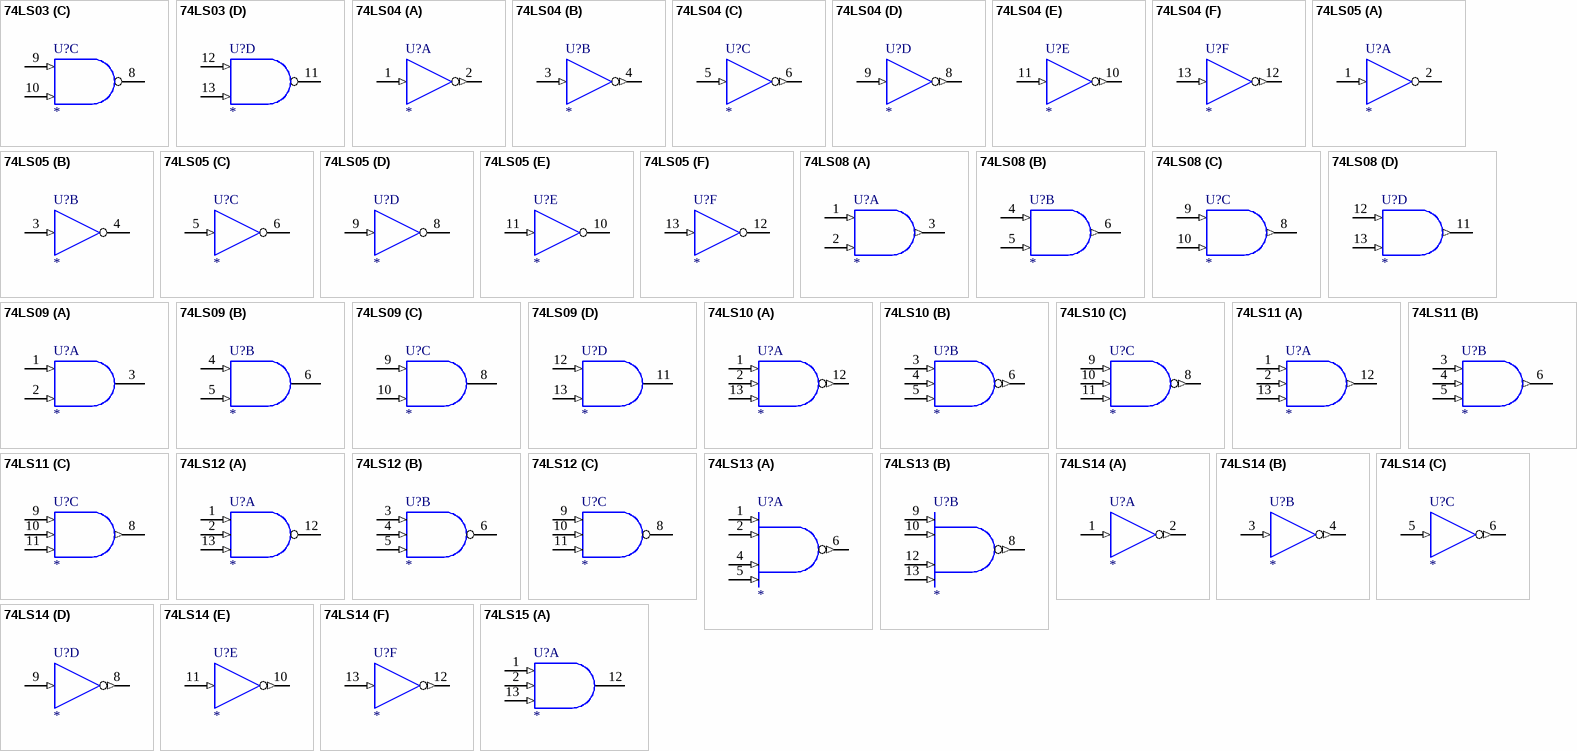
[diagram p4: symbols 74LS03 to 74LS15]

## 74LS03
designator U?
Quad 2-Input Positive-NAND Gate with Open-Collector Output
footprint DIP-14
simulation model 74LS03 (SIMCODE)
part A pins: 1 A (in), 2 B (in), 3 Y (oc), 7 GND (power) hidden to GND, 14 VCC (power) hidden to VCC
part B pins: 4 A (in), 5 B (in), 6 Y (oc), 7 GND (power) hidden to GND, 14 VCC (power) hidden to VCC
part C pins: 7 GND (power) hidden to GND, 8 Y (oc), 9 A (in), 10 B (in), 14 VCC (power) hidden to VCC
part D pins: 7 GND (power) hidden to GND, 11 Y (oc), 12 A (in), 13 B (in), 14 VCC (power) hidden to VCC
1 alternate drawing of the same symbol

## 74LS04
designator U?
Hex Inverter
footprint DIP-14
simulation model 74LS04 (SIMCODE)
part A pins: 1 A (in), 2 Y (out), 7 GND (power) hidden to GND, 14 VCC (power) hidden to VCC
part B pins: 3 A (in), 4 Y (out), 7 GND (power) hidden to GND, 14 VCC (power) hidden to VCC
part C pins: 5 A (in), 6 Y (out), 7 GND (power) hidden to GND, 14 VCC (power) hidden to VCC
part D pins: 7 GND (power) hidden to GND, 8 Y (out), 9 A (in), 14 VCC (power) hidden to VCC
part E pins: 7 GND (power) hidden to GND, 10 Y (out), 11 A (in), 14 VCC (power) hidden to VCC
part F pins: 7 GND (power) hidden to GND, 12 Y (out), 13 A (in), 14 VCC (power) hidden to VCC
1 alternate drawing of the same symbol

## 74LS05
designator U?
Hex Inverter with Open-Collector Output
footprint DIP-14
simulation model 74LS05 (SIMCODE)
part A pins: 1 A (in), 2 Y (oc), 7 GND (power) hidden to GND, 14 VCC (power) hidden to VCC
part B pins: 3 A (in), 4 Y (oc), 7 GND (power) hidden to GND, 14 VCC (power) hidden to VCC
part C pins: 5 A (in), 6 Y (oc), 7 GND (power) hidden to GND, 14 VCC (power) hidden to VCC
part D pins: 7 GND (power) hidden to GND, 8 Y (oc), 9 A (in), 14 VCC (power) hidden to VCC
part E pins: 7 GND (power) hidden to GND, 10 Y (oc), 11 A (in), 14 VCC (power) hidden to VCC
part F pins: 7 GND (power) hidden to GND, 12 Y (oc), 13 A (in), 14 VCC (power) hidden to VCC
2 alternate drawings of the same symbol

## 74LS08
designator U?
Quad 2-Input Positive-AND Gate
footprint DIP-14
simulation model 74LS08 (SIMCODE)
part A pins: 1 A (in), 2 B (in), 3 Y (out), 7 GND (power) hidden to GND, 14 VCC (power) hidden to VCC
part B pins: 4 A (in), 5 B (in), 6 Y (out), 7 GND (power) hidden to GND, 14 VCC (power) hidden to VCC
part C pins: 7 GND (power) hidden to GND, 8 Y (out), 9 A (in), 10 B (in), 14 VCC (power) hidden to VCC
part D pins: 7 GND (power) hidden to GND, 11 Y (out), 12 A (in), 13 B (in), 14 VCC (power) hidden to VCC
1 alternate drawing of the same symbol

## 74LS09
designator U?
Quad 2-Input Positive-AND Gate with Open-Collector Output
footprint DIP-14
simulation model 74LS09 (SIMCODE)
part A pins: 1 A (in), 2 B (in), 3 Y (oc), 7 GND (power) hidden to GND, 14 VCC (power) hidden to VCC
part B pins: 4 A (in), 5 B (in), 6 Y (oc), 7 GND (power) hidden to GND, 14 VCC (power) hidden to VCC
part C pins: 7 GND (power) hidden to GND, 8 Y (oc), 9 A (in), 10 B (in), 14 VCC (power) hidden to VCC
part D pins: 7 GND (power) hidden to GND, 11 Y (oc), 12 A (in), 13 B (in), 14 VCC (power) hidden to VCC
1 alternate drawing of the same symbol

## 74LS10
designator U?
Triple 3-Input Positive-NAND Gate
footprint DIP-14
simulation model 74LS10 (SIMCODE)
part A pins: 1 A (in), 2 B (in), 7 GND (power) hidden to GND, 12 Y (out), 13 C (in), 14 VCC (power) hidden to VCC
part B pins: 3 A (in), 4 B (in), 5 C (in), 6 Y (out), 7 GND (power) hidden to GND, 14 VCC (power) hidden to VCC
part C pins: 7 GND (power) hidden to GND, 8 Y (out), 9 A (in), 10 B (in), 11 C (in), 14 VCC (power) hidden to VCC
1 alternate drawing of the same symbol

## 74LS11
designator U?
Triple 3-Input Positive-AND Gate
footprint DIP-14
simulation model 74LS11 (SIMCODE)
part A pins: 1 A (in), 2 B (in), 7 GND (power) hidden to GND, 12 Y (out), 13 C (in), 14 VCC (power) hidden to VCC
part B pins: 3 A (in), 4 B (in), 5 C (in), 6 Y (out), 7 GND (power) hidden to GND, 14 VCC (power) hidden to VCC
part C pins: 7 GND (power) hidden to GND, 8 Y (out), 9 A (in), 10 B (in), 11 C (in), 14 VCC (power) hidden to VCC
1 alternate drawing of the same symbol

## 74LS12
designator U?
Triple 3-Input Positive-NAND Gate with Open-Collector Output
footprint DIP-14
simulation model 74LS12 (SIMCODE)
part A pins: 1 A (in), 2 B (in), 7 GND (power) hidden to GND, 12 Y (oc), 13 C (in), 14 VCC (power) hidden to VCC
part B pins: 3 A (in), 4 B (in), 5 C (in), 6 Y (oc), 7 GND (power) hidden to GND, 14 VCC (power) hidden to VCC
part C pins: 7 GND (power) hidden to GND, 8 Y (oc), 9 A (in), 10 B (in), 11 C (in), 14 VCC (power) hidden to VCC
1 alternate drawing of the same symbol

## 74LS13
designator U?
Dual 4-Input Positive-NAND Schmitt-Trigger
footprint DIP-14
simulation model 74LS13 (SIMCODE)
part A pins: 1 A (in), 2 B (in), 4 C (in), 5 D (in), 6 Y (out), 7 GND (power) hidden to GND, 14 VCC (power) hidden to VCC
part B pins: 7 GND (power) hidden to GND, 8 Y (out), 9 A (in), 10 B (in), 12 C (in), 13 D (in), 14 VCC (power) hidden to VCC
1 alternate drawing of the same symbol

## 74LS14
designator U?
Hex Schmitt-Trigger Inverter
footprint DIP-14
simulation model 74LS14 (SIMCODE)
part A pins: 1 A (in), 2 Y (out), 7 GND (power) hidden to GND, 14 VCC (power) hidden to VCC
part B pins: 3 A (in), 4 Y (out), 7 GND (power) hidden to GND, 14 VCC (power) hidden to VCC
part C pins: 5 A (in), 6 Y (out), 7 GND (power) hidden to GND, 14 VCC (power) hidden to VCC
part D pins: 7 GND (power) hidden to GND, 8 Y (out), 9 A (in), 14 VCC (power) hidden to VCC
part E pins: 7 GND (power) hidden to GND, 10 Y (out), 11 A (in), 14 VCC (power) hidden to VCC
part F pins: 7 GND (power) hidden to GND, 12 Y (out), 13 A (in), 14 VCC (power) hidden to VCC
1 alternate drawing of the same symbol

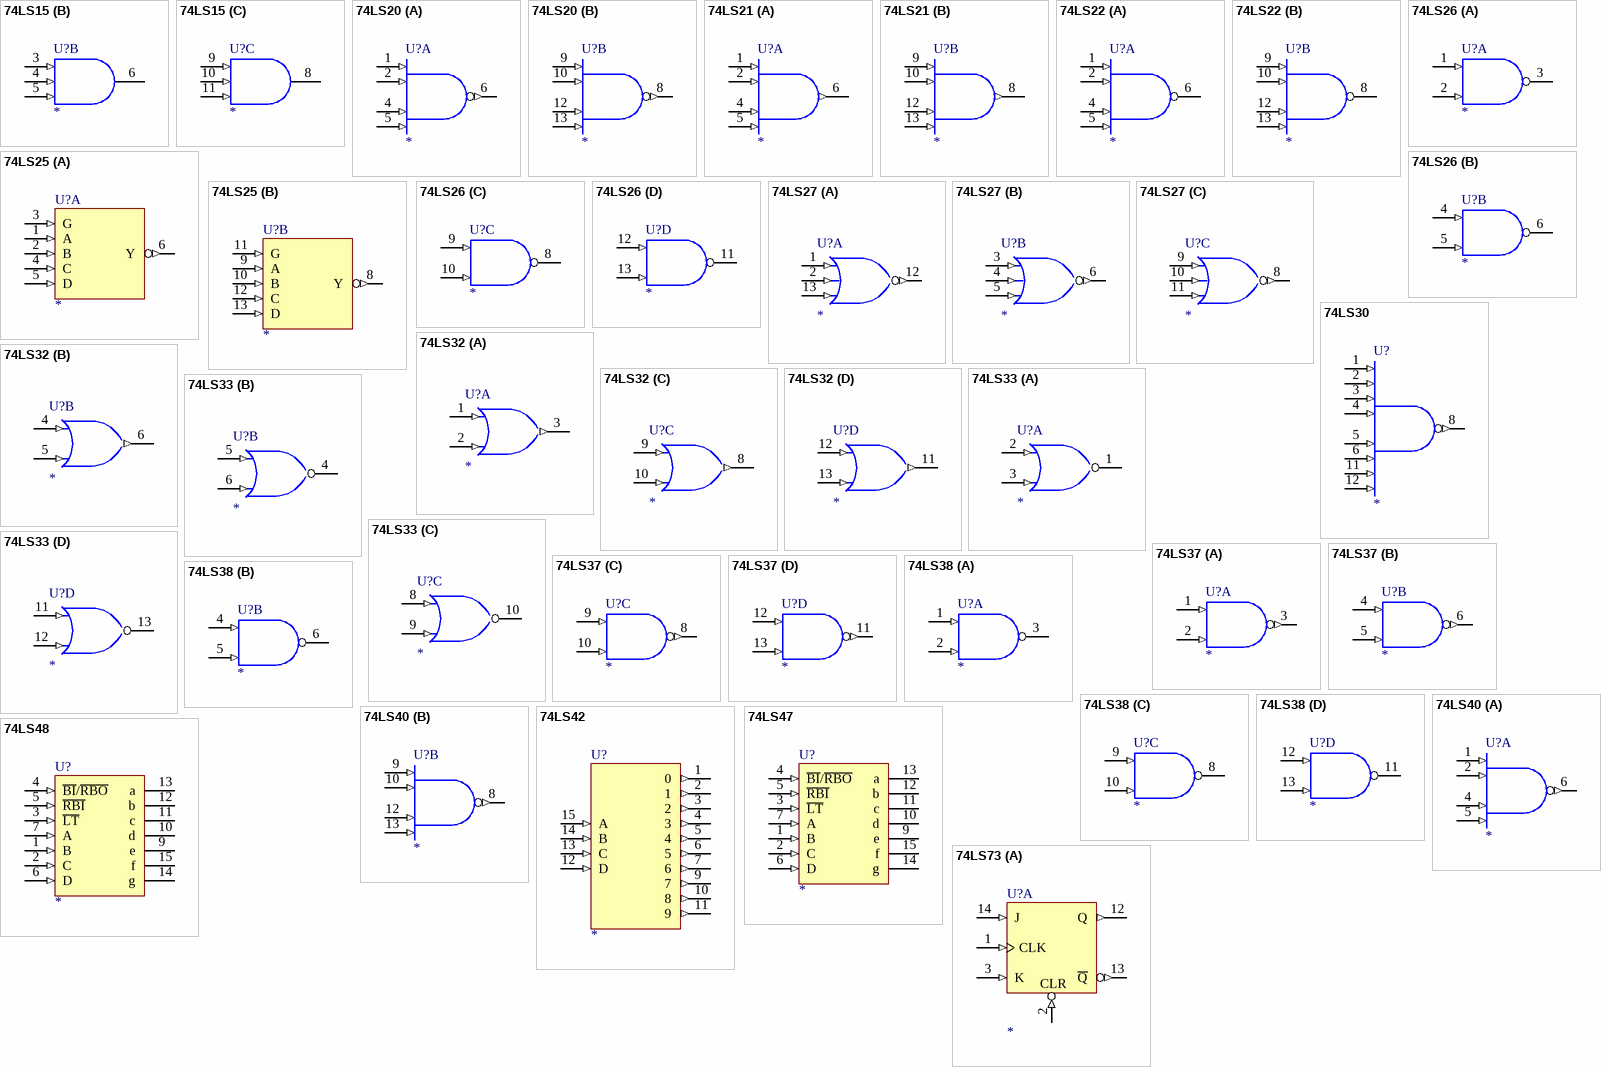
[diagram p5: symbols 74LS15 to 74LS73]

## 74LS15
designator U?
Triple 3-Input Positive-AND Gate with Open-Collector Output
footprint DIP-14
simulation model 74LS15 (SIMCODE)
part A pins: 1 A (in), 2 B (in), 7 GND (power) hidden to GND, 12 Y (oc), 13 C (in), 14 VCC (power) hidden to VCC
part B pins: 3 A (in), 4 B (in), 5 C (in), 6 Y (oc), 7 GND (power) hidden to GND, 14 VCC (power) hidden to VCC
part C pins: 7 GND (power) hidden to GND, 8 Y (oc), 9 A (in), 10 B (in), 11 C (in), 14 VCC (power) hidden to VCC
1 alternate drawing of the same symbol

## 74LS20
designator U?
Dual 4-Input Positive-NAND Gate
footprint DIP-14
simulation model 74LS20 (SIMCODE)
part A pins: 1 A (in), 2 B (in), 4 C (in), 5 D (in), 6 Y (out), 7 GND (power) hidden to GND, 14 VCC (power) hidden to VCC
part B pins: 7 GND (power) hidden to GND, 8 Y (out), 9 A (in), 10 B (in), 12 C (in), 13 D (in), 14 VCC (power) hidden to VCC
2 alternate drawings of the same symbol

## 74LS21
designator U?
Dual 4-Input Positive-AND Gate
footprint DIP-14
simulation model 74LS21 (SIMCODE)
part A pins: 1 A (in), 2 B (in), 4 C (in), 5 D (in), 6 Y (out), 7 GND (power) hidden to GND, 14 VCC (power) hidden to VCC
part B pins: 7 GND (power) hidden to GND, 8 Y (out), 9 A (in), 10 B (in), 12 C (in), 13 D (in), 14 VCC (power) hidden to VCC
2 alternate drawings of the same symbol

## 74LS22
designator U?
Dual 4-Input Positive-NAND Gate with Open-Collector Outputs
footprint DIP-14
simulation model 74LS22 (SIMCODE)
part A pins: 1 A (in), 2 B (in), 4 C (in), 5 D (in), 6 Y (oc), 7 GND (power) hidden to GND, 14 VCC (power) hidden to VCC
part B pins: 7 GND (power) hidden to GND, 8 Y (oc), 9 A (in), 10 B (in), 12 C (in), 13 D (in), 14 VCC (power) hidden to VCC
2 alternate drawings of the same symbol

## 74LS25
designator U?
Dual 4-Input NOR Gate with Strobe
footprint DIP-14
simulation model 74LS25 (SIMCODE)
part A pins: 1 A (in), 2 B (in), 3 G (in), 4 C (in), 5 D (in), 6 Y (out), 7 GND (power) hidden to GND, 14 VCC (power) hidden to VCC
part B pins: 7 GND (power) hidden to GND, 8 Y (out), 9 A (in), 10 B (in), 11 G (in), 12 C (in), 13 D (in), 14 VCC (power) hidden to VCC
1 alternate drawing of the same symbol

## 74LS26
designator U?
High-Voltage Interface Positive-NAND Gate
footprint DIP-14
simulation model 74LS26 (SIMCODE)
part A pins: 1 A (in), 2 B (in), 3 Y (oc), 7 GND (power) hidden to GND, 14 VCC (power) hidden to VCC
part B pins: 4 A (in), 5 B (in), 6 Y (oc), 7 GND (power) hidden to GND, 14 VCC (power) hidden to VCC
part C pins: 7 GND (power) hidden to GND, 8 Y (oc), 9 A (in), 10 B (in), 14 VCC (power) hidden to VCC
part D pins: 7 GND (power) hidden to GND, 11 Y (oc), 12 A (in), 13 B (in), 14 VCC (power) hidden to VCC
1 alternate drawing of the same symbol

## 74LS27
designator U?
Triple 3-Input Positive-NOR Gate
footprint DIP-14
simulation model 74LS27 (SIMCODE)
part A pins: 1 A (in), 2 B (in), 7 GND (power) hidden to GND, 12 Y (out), 13 C (in), 14 VCC (power) hidden to VCC
part B pins: 3 A (in), 4 B (in), 5 C (in), 6 Y (out), 7 GND (power) hidden to GND, 14 VCC (power) hidden to VCC
part C pins: 7 GND (power) hidden to GND, 8 Y (out), 9 A (in), 10 B (in), 11 C (in), 14 VCC (power) hidden to VCC
1 alternate drawing of the same symbol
